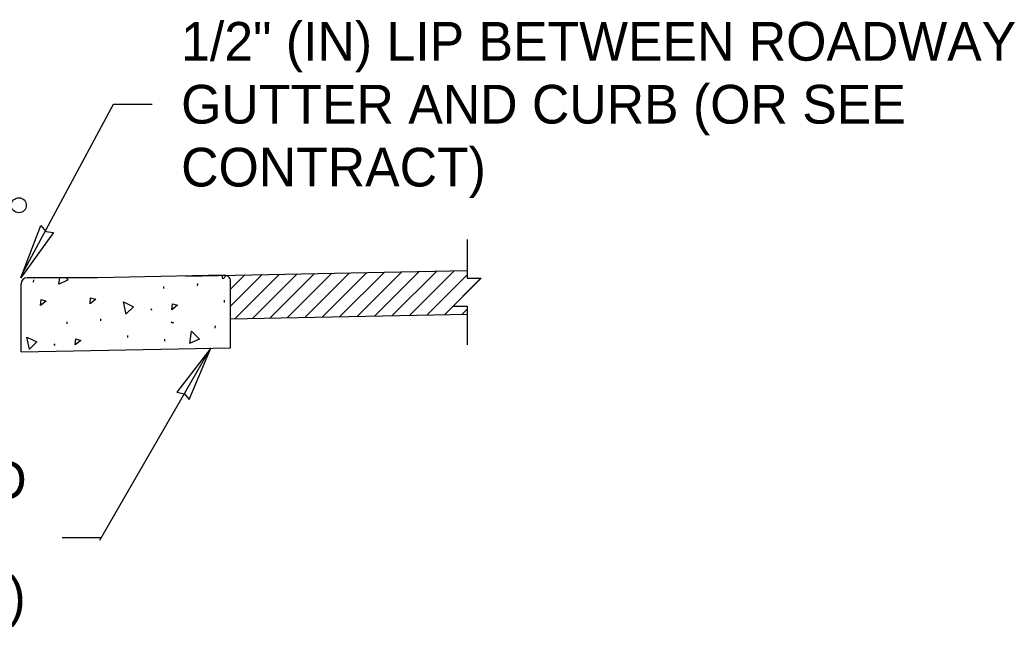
# Model space of a CAD drawing. Extents: x 99862 to 103151, y 100000 to 105076.
# Drawn here: x 100902.1 to 101313.5, y 103814.8 to 104065.8 of the extents above; entities that cross this region are included whole.
import ezdxf

# ---------------------------------------------------------------- set-up
doc = ezdxf.new("R2010")
doc.units = 0
for name, color, linetype in [('Level 13', 7, 'Continuous'), ('Level 15', 7, 'Continuous'), ('Level 16', 7, 'Continuous'), ('Level 20', 7, 'Continuous'), ('Level 48', 7, 'Continuous')]:
    doc.layers.add(name, color=color, linetype=linetype)

msp = doc.modelspace()

# ---------------------------------------------------------------- linework, layer by layer
at = {"layer": 'Level 13'}
for p, q in [((100907.74, 103957.44), (100907.8, 103958.31)), ((100907.74, 103957.44), (100907.8, 103958.31)), ((100975.48, 103955.92), (100975.54, 103956.79)), ((100975.48, 103955.92), (100975.54, 103956.79)), ((100961.55, 103954.72), (100961.61, 103955.6)), ((100961.55, 103954.72), (100961.61, 103955.6)), ((100986.6, 103949), (100986.66, 103949.88)), ((100986.6, 103949), (100986.66, 103949.88)), ((100956.11, 103946.5), (100956.47, 103945.78)), ((100956.11, 103946.5), (100956.47, 103945.78)), ((100921.58, 103940.18), (100921.64, 103941.05)), ((100921.58, 103940.18), (100921.64, 103941.05)), ((100935.51, 103941.37), (100935.57, 103942.24)), ((100935.51, 103941.37), (100935.57, 103942.24)), ((100964.57, 103940.99), (100965.08, 103940.61)), ((100964.57, 103940.99), (100965.08, 103940.61)), ((100964.97, 103940.92), (100965.49, 103940.54)), ((100964.97, 103940.92), (100965.49, 103940.54)), ((100982.79, 103938.44), (100982.85, 103939.31)), ((100982.79, 103938.44), (100982.85, 103939.31)), ((100916.14, 103931.95), (100916.5, 103931.23)), ((100916.14, 103931.95), (100916.5, 103931.23)), ((100946.63, 103934.46), (100946.69, 103935.33)), ((100946.63, 103934.46), (100946.69, 103935.33)), ((100961.9, 103933.01), (100961.96, 103933.88)), ((100961.9, 103933.01), (100961.96, 103933.88))]:
    msp.add_line(p, q, dxfattribs=at)
for points in [[(100918.18, 103956.52), (100918.55, 103959.18)], [(100918.18, 103956.52), (100918.55, 103959.18)], [(100921.23, 103959.18), (100922.07, 103958.31), (100918.27, 103956.55)], [(100921.23, 103959.18), (100922.07, 103958.31), (100918.27, 103956.55)], [(100985.95, 103958.75), (100985.64, 103960.21)], [(100985.95, 103958.75), (100985.64, 103960.21)], [(100987.3, 103960.09), (100986.02, 103958.81)], [(100987.3, 103960.09), (100986.02, 103958.81)], [(100910.58, 103947.8), (100910.83, 103950.25), (100912.95, 103949.6), (100910.58, 103947.8)], [(100910.58, 103947.8), (100910.83, 103950.25), (100912.95, 103949.6), (100910.58, 103947.8)], [(100931.05, 103948.49), (100931.29, 103950.94), (100933.41, 103950.3), (100931.05, 103948.49)], [(100931.05, 103948.49), (100931.29, 103950.94), (100933.41, 103950.3), (100931.05, 103948.49)], [(100945.98, 103944.2), (100944.9, 103949.21), (100949.01, 103947.21), (100946.04, 103944.26)], [(100945.98, 103944.2), (100944.9, 103949.21), (100949.01, 103947.21), (100946.04, 103944.26)], [(100964.91, 103946.02), (100965.15, 103948.47), (100967.27, 103947.83), (100964.91, 103946.02)], [(100964.91, 103946.02), (100965.15, 103948.47), (100967.27, 103947.83), (100964.91, 103946.02)], [(100972.34, 103932.09), (100973.05, 103937.16), (100976.23, 103933.88), (100972.43, 103932.12)], [(100972.34, 103932.09), (100973.05, 103937.16), (100976.23, 103933.88), (100972.43, 103932.12)], [(100906, 103929.65), (100904.93, 103934.66), (100909.04, 103932.67), (100906.07, 103929.71)], [(100906, 103929.65), (100904.93, 103934.66), (100909.04, 103932.67), (100906.07, 103929.71)], [(100924.94, 103931.47), (100925.18, 103933.93), (100927.3, 103933.28), (100924.94, 103931.47)], [(100924.94, 103931.47), (100925.18, 103933.93), (100927.3, 103933.28), (100924.94, 103931.47)]]:
    msp.add_lwpolyline(points, dxfattribs=at)
at = {"layer": 'Level 15'}
for p, q in [((100903.04, 103960.65), (100940.7, 104030.92)), ((100903.04, 103960.65), (100940.7, 104030.92)), ((100940.7, 104030.92), (100956.7, 104030.92)), ((100940.7, 104030.92), (100956.7, 104030.92)), ((100987.57, 103960.04), (100987.78, 103960.25)), ((100980.88, 103930.11), (100935.01, 103850.66)), ((100980.88, 103930.11), (100935.01, 103850.66)), ((100935.54, 103851.65), (100919.54, 103851.65)), ((100935.54, 103851.65), (100919.54, 103851.65))]:
    msp.add_line(p, q, dxfattribs=at)
for points in [[(100902.5, 103959.2), (100910.65, 103980.74), (100912.78, 103978.39), (100915.91, 103977.92)], [(100980.92, 103930.15), (100966.92, 103911.87), (100970.04, 103911.29), (100972.09, 103908.88)], [(100980.92, 103930.15), (100966.92, 103911.87), (100970.04, 103911.29), (100972.09, 103908.88)]]:
    msp.add_lwpolyline(points, close=True, dxfattribs=at)
msp.add_lwpolyline([(101086.94, 103975.04), (101086.94, 103959.04), (101092.75, 103959.04), (101081.13, 103947.43), (101086.94, 103947.43), (101086.94, 103931.43)], dxfattribs=at)
msp.add_circle((100901.61, 103989.18), 3.08, dxfattribs=at)
msp.add_circle((100901.61, 103989.18), 3.08, dxfattribs=at)
at = {"layer": 'Level 16'}
for p, q in [((100902.55, 103928.55), (100902.55, 103956.68)), ((100934.11, 103959.18), (100905.05, 103959.18)), ((100986.56, 103960.23), (100934.11, 103959.18)), ((100989.11, 103930.28), (100989.11, 103957.73)), ((100902.55, 103928.55), (100989.11, 103930.28))]:
    msp.add_line(p, q, dxfattribs=at)
for centre, start, end in [((100905.05, 103956.68), 90, 180), ((100986.61, 103957.73), 0, 91.1458), ((100986.61, 103957.73), 0, 91.1458)]:
    msp.add_arc(centre, 2.5, start, end, dxfattribs=at)
at = {"layer": 'Level 48'}
for p, q in [((100970.57, 103959.91), (101086.94, 103962.23)), ((100989.11, 103947.43), (101002.21, 103960.54)), ((100991.06, 103942.32), (101009.43, 103960.68)), ((100998.28, 103942.46), (101016.64, 103960.83)), ((101005.49, 103942.6), (101023.86, 103960.97)), ((101012.71, 103942.75), (101031.07, 103961.12)), ((101019.92, 103942.89), (101038.29, 103961.26)), ((101027.14, 103943.04), (101045.51, 103961.41)), ((101034.35, 103943.18), (101052.72, 103961.55)), ((101041.57, 103943.33), (101059.94, 103961.69)), ((101048.78, 103943.47), (101067.15, 103961.84)), ((101056, 103943.61), (101074.37, 103961.98)), ((101063.21, 103943.76), (101081.58, 103962.13)), ((100989.11, 103954.51), (100995, 103960.39)), ((101070.43, 103943.9), (101086.94, 103960.41)), ((101077.65, 103944.05), (101092.64, 103959.04)), ((100989.11, 103942.28), (101086.94, 103944.23)), ((101084.86, 103944.19), (101086.94, 103946.27))]:
    msp.add_line(p, q, dxfattribs=at)

# ---------------------------------------------------------------- texts
at = {"layer": 'Level 20'}
for s, p in [('1/2" (IN) LIP BETWEEN ROADWAY ', (100968.71, 104048.93)), ('GUTTER AND CURB (OR SEE', (100968.71, 104022.93)), ('CONTRACT)', (100968.71, 103996.93)), ('DEPRESSED', (100772.88, 103867.64)), ('(SEE NOTE 3)', (100764.15, 103819.64))]:
    msp.add_text(s, height=16, dxfattribs=at).set_placement(p)

doc.saveas('drawing.dxf')
